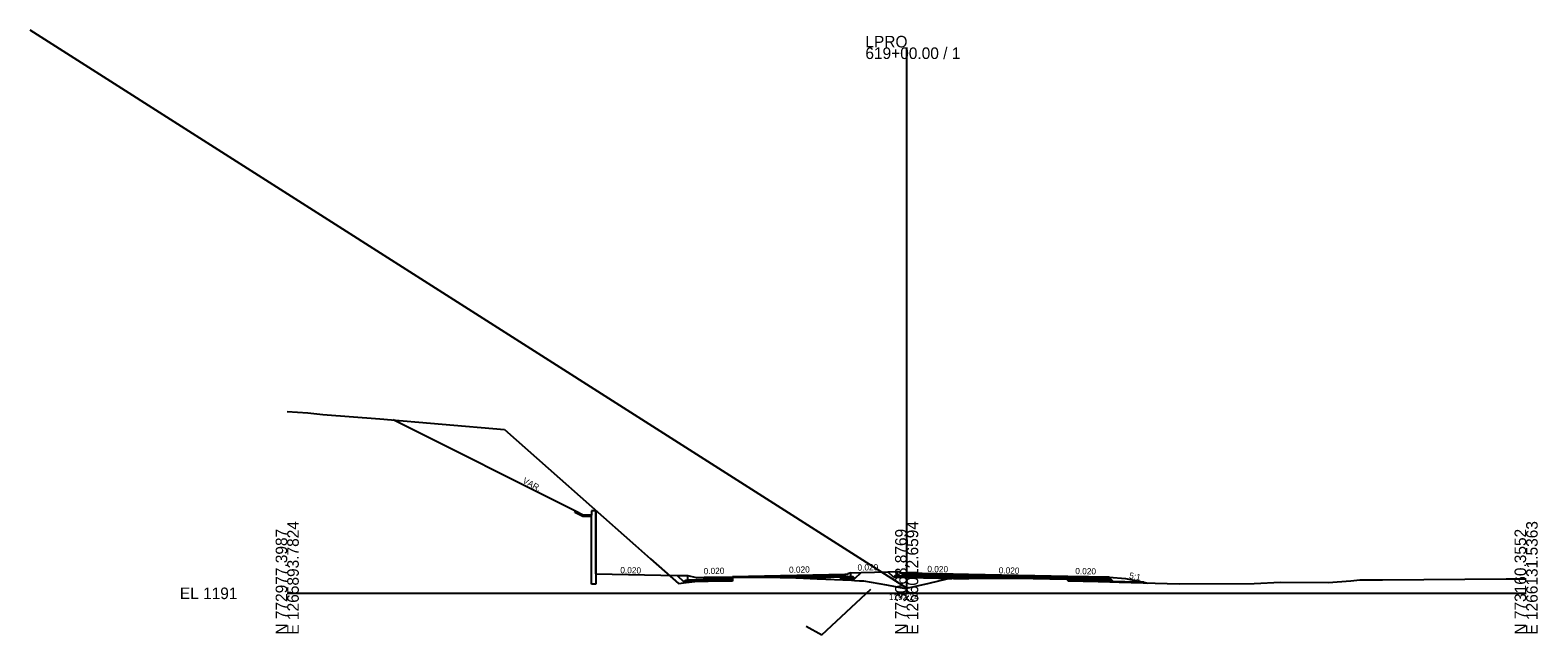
# Model space of a CAD drawing. Extents: x -3833 to 1267678, y -522 to 773248.
# Drawn here: x 2937.8 to 3302.8, y -10 to 136.3 of the extents above; entities that cross this region are included whole.
import ezdxf

# ---------------------------------------------------------------- set-up
doc = ezdxf.new("R2010")
doc.units = 0
for name, color, linetype in [('Exist Cross Section Cell', 7, 'Continuous'), ('Exist XS Center Line Elevation Label', 7, 'Continuous'), ('Exist XS Ground Line', 7, 'Continuous'), ('Prop CMT DNC', 7, 'Continuous'), ('Prop CMT Pvmt Course 1', 7, 'Continuous'), ('Prop CMT Pvmt Course 2', 7, 'Continuous'), ('Prop CMT Pvmt Course 3', 7, 'Continuous'), ('Prop CMT Pvmt Course 4', 7, 'Continuous'), ('Prop CMT Shld Paved Course 1', 7, 'Continuous'), ('Prop CMT Shld Paved Course 2', 7, 'Continuous'), ('Prop CMT Shld Paved Course 4', 7, 'Continuous'), ('Prop CMT Slope Grass', 7, 'Continuous'), ('Prop CMT Subgrade Earthwork', 7, 'Continuous'), ('Prop Conc Curb and Gutter', 7, 'Continuous'), ('Prop Conc Island Cover', 7, 'Continuous'), ('Prop Corridor Mesh Bottom', 7, 'Continuous'), ('Prop XS Ditch Slope Text', 7, 'Continuous'), ('Prop XS Finish Grade', 7, 'Continuous'), ('Prop XS SE Text', 7, 'Continuous'), ('Scratch_Level_1', 7, 'Continuous'), ('Scratch_Level_5', 7, 'Continuous')]:
    doc.layers.add(name, color=color, linetype=linetype)

msp = doc.modelspace()

# ---------------------------------------------------------------- linework, layer by layer
at = {"layer": 'Exist Cross Section Cell'}
for p, q in [((3150, 0), (3150, 132.12)), ((3000, 0), (3150, 0)), ((3150, 0), (3300, 0))]:
    msp.add_line(p, q, dxfattribs=at)
at = {"layer": 'Exist XS Ground Line'}
for p, q in [((3000, 44.04), (3004.97, 43.68)), ((3004.97, 43.68), (3008.66, 43.28)), ((3008.66, 43.28), (3022.44, 42.25)), ((3022.44, 42.25), (3052.63, 39.62)), ((3052.63, 39.62), (3084.3, 11.56)), ((3084.3, 11.56), (3087.95, 8.33)), ((3087.95, 8.33), (3094.75, 2.4)), ((3096.63, 2.63), (3107.07, 3.85)), ((3107.07, 3.85), (3108.26, 3.87)), ((3108.26, 3.87), (3111.3, 3.94)), ((3111.3, 3.94), (3119.34, 3.8)), ((3119.34, 3.8), (3123.3, 3.73)), ((3123.3, 3.73), (3128.3, 3.52)), ((3160.97, 3.61), (3163.36, 3.66)), ((3163.36, 3.66), (3164.79, 3.68)), ((3164.79, 3.68), (3169.2, 3.67)), ((3169.2, 3.67), (3176.55, 3.67)), ((3176.55, 3.67), (3184.64, 3.49)), ((3094.75, 2.4), (3096.63, 2.63)), ((3128.3, 3.52), (3136.63, 3.18)), ((3136.63, 3.18), (3137.39, 3.12)), ((3137.39, 3.12), (3138.58, 3.02)), ((3138.58, 3.02), (3139.51, 3)), ((3139.51, 3), (3145.1, 2.02)), ((3145.1, 2.02), (3149.68, 1.17)), ((3149.68, 1.17), (3150, 1.24)), ((3150, 1.24), (3155.48, 2.44)), ((3155.48, 2.44), (3159.83, 3.5)), ((3159.83, 3.5), (3160.97, 3.61)), ((3184.64, 3.49), (3188.72, 3.39)), ((3188.72, 3.39), (3191.99, 3.14)), ((3191.99, 3.14), (3193.3, 3.04)), ((3193.3, 3.04), (3196.87, 2.88)), ((3196.87, 2.88), (3201.43, 2.68)), ((3201.43, 2.68), (3215.95, 2.27)), ((3215.95, 2.27), (3234.13, 2.4)), ((3234.13, 2.4), (3240.49, 2.66)), ((3240.49, 2.66), (3252.03, 2.59)), ((3252.03, 2.59), (3257.58, 3.02)), ((3257.58, 3.02), (3259.73, 3.25)), ((3259.73, 3.25), (3265.23, 3.29)), ((3265.23, 3.29), (3295.18, 3.53)), ((3295.18, 3.53), (3298.85, 3.53)), ((3298.85, 3.53), (3300, 3.53))]:
    msp.add_line(p, q, dxfattribs=at)
at = {"layer": 'Prop CMT Pvmt Course 1'}
for p, q in [((3135, 4.56), (3107.86, 4.01)), ((3107.86, 3.87), (3135, 4.31)), ((3107.86, 4.01), (3107.86, 4.01)), ((3107.86, 3.76), (3107.86, 3.76)), ((3107.86, 3.76), (3107.86, 3.76)), ((3135, 4.31), (3135, 4.56)), ((3135, 4.31), (3135, 4.31)), ((3189, 4.08), (3165, 4.56)), ((3165, 4.56), (3165, 4.31)), ((3165, 4.31), (3165, 4.31)), ((3165, 4.31), (3189, 3.83)), ((3189, 3.83), (3189, 4.08)), ((3189, 4.08), (3189, 4.08)), ((3189, 3.83), (3189, 3.83)), ((3189, 3.83), (3189, 3.83))]:
    msp.add_line(p, q, dxfattribs=at)
msp.add_lwpolyline([(3107.86, 4.01), (3107.86, 3.86), (3107.86, 3.76)], dxfattribs=at)
at = {"layer": 'Prop CMT Pvmt Course 2'}
for p, q in [((3135, 4.31), (3135, 4.31)), ((3135, 4.31), (3135, 3.98)), ((3135, 3.98), (3135, 3.98)), ((3135, 3.98), (3135, 3.97)), ((3135, 3.97), (3135, 3.97)), ((3150, 4.61), (3149.23, 4.59)), ((3149.23, 4.26), (3150, 4.28)), ((3165, 4.31), (3150, 4.61)), ((3150, 4.28), (3165, 3.97)), ((3165, 3.97), (3165, 4.31)), ((3165, 4.31), (3165, 4.31)), ((3165, 3.97), (3165, 3.97)), ((3165, 3.97), (3165, 3.97)), ((3165, 3.97), (3165, 3.97))]:
    msp.add_line(p, q, dxfattribs=at)
at = {"layer": 'Prop CMT Pvmt Course 3'}
for p, q in [((3137.01, 4.02), (3135, 3.97)), ((3137.46, 3.57), (3137.01, 4.02)), ((3146.94, 4.01), (3147.22, 4.3)), ((3147.22, 4.3), (3149.23, 4.26))]:
    msp.add_line(p, q, dxfattribs=at)
at = {"layer": 'Prop CMT Pvmt Course 4'}
for p, q in [((3134, 4.54), (3134, 3.29)), ((3135, 3.97), (3135, 3.98)), ((3135, 3.97), (3135, 3.97)), ((3147.22, 4.3), (3146.81, 3.88)), ((3146.81, 3.88), (3165, 3.52)), ((3147.72, 4.29), (3147.22, 4.3)), ((3165, 3.97), (3150, 4.28)), ((3165, 3.52), (3165, 3.97)), ((3165, 3.97), (3165, 3.97)), ((3165, 3.97), (3165, 3.97)), ((3134, 3.5), (3137.46, 3.57))]:
    msp.add_line(p, q, dxfattribs=at)
at = {"layer": 'Prop CMT Shld Paved Course 1'}
for p, q in [((3101, 3.88), (3107.86, 4.01)), ((3101, 3.63), (3101, 3.88)), ((3101, 3.88), (3101, 3.88)), ((3107.86, 3.76), (3101, 3.63)), ((3107.86, 3.76), (3107.86, 3.76)), ((3135, 4.56), (3135, 4.56)), ((3135, 4.56), (3135, 4.31)), ((3135, 4.31), (3135, 4.31)), ((3135, 4.31), (3135, 4.31)), ((3150, 4.86), (3149.23, 4.84)), ((3149.23, 4.59), (3150, 4.61)), ((3165, 4.56), (3150, 4.86)), ((3150, 4.61), (3165, 4.31)), ((3165, 4.31), (3165, 4.56)), ((3165, 4.56), (3165, 4.56)), ((3165, 4.31), (3165, 4.31)), ((3165, 4.31), (3165, 4.31)), ((3189, 4.08), (3189, 3.83)), ((3199, 3.88), (3189, 4.08)), ((3189, 3.83), (3199.26, 3.62)), ((3199.26, 3.62), (3199, 3.88)), ((3101, 3.63), (3101, 3.63)), ((3101, 3.63), (3101, 3.63))]:
    msp.add_line(p, q, dxfattribs=at)
msp.add_lwpolyline([(3107.86, 4.01), (3107.86, 3.86), (3107.86, 3.86), (3107.86, 3.86)], dxfattribs=at)
at = {"layer": 'Prop CMT Shld Paved Course 2'}
for p, q in [((3101, 3.63), (3107.86, 3.76)), ((3107.86, 3.86), (3108.3, 3.88)), ((3108.3, 3.88), (3107.86, 3.86)), ((3107.86, 3.76), (3107.86, 3.86)), ((3107.86, 3.86), (3107.86, 3.76)), ((3107.86, 3.76), (3107.86, 3.43)), ((3107.86, 3.76), (3107.86, 3.76)), ((3107.86, 3.76), (3107.86, 3.76)), ((3108.3, 3.88), (3109.24, 3.9)), ((3109.24, 3.9), (3108.3, 3.88)), ((3109.24, 3.9), (3111.18, 3.94)), ((3111.18, 3.94), (3109.24, 3.9)), ((3111.18, 3.94), (3111.3, 3.94)), ((3111.45, 3.94), (3111.18, 3.94)), ((3111.3, 3.94), (3114.14, 3.89)), ((3119.34, 3.99), (3111.45, 3.94)), ((3114.14, 3.89), (3114.14, 3.89)), ((3114.14, 3.89), (3119.34, 3.8)), ((3123.3, 4.07), (3119.34, 3.99)), ((3119.34, 3.99), (3119.34, 3.99)), ((3119.34, 3.8), (3119.34, 3.8)), ((3119.34, 3.8), (3123.15, 3.74)), ((3123.15, 3.74), (3123.15, 3.74)), ((3123.15, 3.74), (3123.3, 3.74)), ((3128.3, 4.17), (3123.3, 4.07)), ((3123.3, 4.07), (3123.3, 4.07)), ((3123.3, 4.07), (3123.3, 4.07)), ((3123.3, 3.74), (3128.3, 3.84)), ((3123.3, 3.74), (3123.3, 3.74)), ((3123.3, 3.74), (3123.3, 3.74)), ((3135, 4.31), (3128.3, 4.17)), ((3128.3, 4.17), (3128.3, 4.17)), ((3128.3, 3.84), (3135, 3.97)), ((3128.3, 3.84), (3128.3, 3.84)), ((3135, 3.97), (3135, 4.31)), ((3135, 3.97), (3135, 3.97)), ((3165, 3.97), (3165, 4.31)), ((3165, 4.31), (3165, 4.31)), ((3165, 4.31), (3169.2, 4.22)), ((3169.2, 3.89), (3165, 3.97)), ((3165, 3.97), (3165, 3.97)), ((3165, 3.97), (3165, 3.97)), ((3169.2, 4.22), (3169.2, 4.22)), ((3169.2, 4.22), (3176.55, 4.08)), ((3176.55, 3.74), (3169.2, 3.89)), ((3169.2, 3.89), (3169.2, 3.89)), ((3176.55, 4.08), (3184.64, 3.91)), ((3184.64, 3.58), (3176.55, 3.74)), ((3184.64, 3.91), (3184.64, 3.91)), ((3184.64, 3.91), (3188.72, 3.83)), ((3188.72, 3.83), (3188.72, 3.83)), ((3188.72, 3.83), (3189, 3.83)), ((3189, 3.83), (3189, 3.83)), ((3189, 3.83), (3189, 3.49)), ((3189, 3.83), (3189, 3.5)), ((3199.26, 3.62), (3189, 3.83)), ((3101, 3.29), (3101, 3.63)), ((3107.86, 3.43), (3101, 3.29)), ((3188.72, 3.5), (3184.64, 3.58)), ((3184.64, 3.58), (3184.64, 3.58)), ((3189, 3.49), (3188.72, 3.5)), ((3188.72, 3.5), (3188.72, 3.5)), ((3189, 3.5), (3199.59, 3.29)), ((3189, 3.49), (3189, 3.49)), ((3189, 3.49), (3189, 3.49)), ((3199.59, 3.29), (3199.26, 3.62))]:
    msp.add_line(p, q, dxfattribs=at)
at = {"layer": 'Prop CMT Shld Paved Course 4'}
for p, q in [((3096.03, 2.74), (3096.5, 3.2)), ((3107.86, 2.97), (3096.03, 2.74)), ((3096.5, 3.2), (3097, 3.21)), ((3097, 3.21), (3107.86, 3.43)), ((3107.86, 3.43), (3107.86, 2.97)), ((3189, 3.5), (3189, 3.04)), ((3199.09, 3.3), (3189, 3.5)), ((3189, 3.04), (3200.06, 2.82)), ((3199.59, 3.29), (3199.09, 3.3)), ((3200.06, 2.82), (3199.59, 3.29))]:
    msp.add_line(p, q, dxfattribs=at)
at = {"layer": 'Prop CMT Slope Grass'}
for p, q in [((3094.42, 4.35), (3097, 4.3)), ((3136.51, 4.99), (3138.95, 5.05)), ((3145.47, 5.22), (3147.56, 5.27)), ((3199, 3.88), (3203, 3.56)), ((3203, 3.56), (3207.45, 2.67))]:
    msp.add_line(p, q, dxfattribs=at)
at = {"layer": 'Prop CMT Subgrade Earthwork'}
for p, q in [((3094.42, 4.35), (3096.03, 2.74)), ((3107.86, 3.86), (3107.86, 2.97)), ((3137.46, 3.57), (3138.95, 5.05)), ((3146.81, 3.88), (3145.47, 5.22)), ((3165, 3.52), (3146.81, 3.88)), ((3165, 3.68), (3165, 3.52)), ((3107.86, 2.97), (3096.03, 2.74)), ((3137.46, 3.57), (3134, 3.5)), ((3134, 3.5), (3134, 3.29)), ((3189, 3.37), (3189, 3.04)), ((3207.45, 2.67), (3189, 3.04))]:
    msp.add_line(p, q, dxfattribs=at)
at = {"layer": 'Prop Conc Curb and Gutter'}
for p, q in [((3069.62, 19.6), (3069.77, 19.9)), ((3071.62, 18.6), (3069.62, 19.6)), ((3071.7, 18.93), (3069.77, 19.9)), ((3073.7, 18.6), (3071.62, 18.6)), ((3073.7, 18.93), (3071.7, 18.93)), ((3073.69, 2.21), (3073.7, 18.93)), ((3074.7, 19.93), (3073.7, 19.93)), ((3073.7, 19.93), (3073.7, 18.93)), ((3074.7, 19.93), (3074.7, 19.94)), ((3074.7, 19.94), (3074.7, 19.93)), ((3074.7, 19.93), (3074.7, 19.93)), ((3074.7, 19.93), (3074.7, 19.93)), ((3074.7, 19.93), (3074.7, 3.35)), ((3097, 3.21), (3097, 4.3)), ((3097, 4.3), (3099, 3.8)), ((3099, 3.8), (3101, 3.88)), ((3099, 3.8), (3099, 3.8)), ((3099, 3.8), (3099, 3.8)), ((3101, 3.88), (3101, 3.29)), ((3135.75, 4.57), (3135, 4.56)), ((3135, 4.56), (3135, 4.56)), ((3135, 4.56), (3135, 3.97)), ((3135, 3.97), (3136.51, 4.01)), ((3135, 3.97), (3135, 3.97)), ((3135, 3.97), (3135, 3.97)), ((3136.51, 4.99), (3135.75, 4.74)), ((3135.75, 4.74), (3135.75, 4.74)), ((3135.75, 4.74), (3135.75, 4.57)), ((3135.75, 4.57), (3135.75, 4.57)), ((3136.51, 4.01), (3136.51, 4.99)), ((3136.51, 4.01), (3136.51, 4.01)), ((3148.48, 5.03), (3147.72, 5.27)), ((3147.72, 5.27), (3147.72, 4.29)), ((3147.72, 4.29), (3147.72, 4.29)), ((3147.72, 4.29), (3149.23, 4.26)), ((3148.48, 5.02), (3148.48, 5.03)), ((3148.48, 4.86), (3148.48, 5.02)), ((3149.23, 4.84), (3148.48, 4.86)), ((3148.48, 4.86), (3148.48, 4.86)), ((3149.23, 4.26), (3149.23, 4.84)), ((3149.23, 4.84), (3149.23, 4.84)), ((3149.23, 4.26), (3149.23, 4.26)), ((3149.23, 4.26), (3149.23, 4.26)), ((3074.7, 2.21), (3073.69, 2.21)), ((3073.69, 2.21), (3073.69, 2.21)), ((3074.7, 3.35), (3074.7, 2.22)), ((3074.7, 2.22), (3074.7, 2.21)), ((3099, 3.25), (3097, 3.21)), ((3097, 3.21), (3097, 3.21)), ((3097, 3.21), (3097, 3.21)), ((3101, 3.29), (3099, 3.25)), ((3099, 3.25), (3099, 3.25)), ((3101, 3.29), (3101, 3.29))]:
    msp.add_line(p, q, dxfattribs=at)
at = {"layer": 'Prop Conc Island Cover'}
for p, q in [((3136.51, 4.74), (3136.51, 4.99)), ((3147.72, 5.27), (3147.72, 5.02))]:
    msp.add_line(p, q, dxfattribs=at)
at = {"layer": 'Prop Corridor Mesh Bottom'}
for p, q in [((3135, 4.56), (3135, 4.31)), ((3165, 4.56), (3165, 4.31)), ((3189, 4.08), (3189, 3.83))]:
    msp.add_line(p, q, dxfattribs=at)
msp.add_lwpolyline([(3107.86, 4.01), (3107.86, 3.86), (3107.86, 3.76)], dxfattribs=at)
at = {"layer": 'Prop XS Finish Grade'}
for p, q in [((3069.77, 19.9), (3025.63, 41.97)), ((3071.7, 18.93), (3069.77, 19.9)), ((3073.7, 18.93), (3071.7, 18.93)), ((3074.7, 19.93), (3073.7, 19.93)), ((3073.7, 19.93), (3073.7, 18.93)), ((3074.7, 4.74), (3074.7, 19.93)), ((3074.7, 4.74), (3094.42, 4.35)), ((3138.95, 5.05), (3145.47, 5.22)), ((3147.56, 5.27), (3147.72, 5.27)), ((3207.45, 2.67), (3208.37, 2.48))]:
    msp.add_line(p, q, dxfattribs=at)
at = {"layer": 'Scratch_Level_1'}
msp.add_line((3150, 1.24), (2937.75, 136.3), dxfattribs=at)
at = {"layer": 'Scratch_Level_5'}
for p, q in [((3129.47, -10.05), (3141.33, 0.98)), ((3125.69, -7.94), (3129.47, -10.05))]:
    msp.add_line(p, q, dxfattribs=at)

# ---------------------------------------------------------------- texts
at = {"layer": 'Exist Cross Section Cell'}
for s, p in [('619+00.00 / 1', (3140, 129.32)), ('LPRO', (3140, 132.12)), ('EL 1191', (2974, -1.4))]:
    msp.add_text(s, height=2.8, dxfattribs=at).set_placement(p)
for s, p in [('N 772977.3987', (3000, -10)), ('E 1265893.7824', (3002.8, -10)), ('N 773068.8769', (3150, -10)), ('E 1266012.6594', (3152.8, -10)), ('N 773160.3552', (3300, -10)), ('E 1266131.5363', (3302.8, -10))]:
    msp.add_text(s, height=2.8, rotation=90, dxfattribs=at).set_placement(p)
at = {"layer": 'Exist XS Center Line Elevation Label'}
msp.add_text('1192.24', height=1.5, dxfattribs=at).set_placement((3145.69, -1.63))
at = {"layer": 'Prop CMT DNC'}
for p in [(3090.8, 5.85), (3099, 3.8), (3101, 3.88), (3101, 3.88), (3107.86, 4.01), (3107.86, 4.01), (3135, 4.56), (3135, 4.56), (3135.75, 4.57), (3148.48, 4.86), (3150, 4.86), (3165, 4.56), (3165, 4.56), (3189, 4.08), (3189, 4.08), (3199, 3.88)]:
    msp.add_text('X', height=0.00025, dxfattribs=at).set_placement(p)
at = {"layer": 'Prop XS Ditch Slope Text'}
for s, rotation, p in [('VAR.', 331.3485, (3056.86, 26.82)), ('5:1', 348.3072, (3203.78, 3.64))]:
    msp.add_text(s, height=1.5, rotation=rotation, dxfattribs=at).set_placement(p)
at = {"layer": 'Prop XS SE Text'}
for rotation, p in [(358.8542, (3080.65, 4.88)), (1.397, (3100.86, 4.61)), (1.397, (3121.53, 4.93)), (1.299, (3138.11, 5.48)), (358.8542, (3155, 5.16)), (358.8542, (3172.28, 4.83)), (358.8542, (3190.82, 4.66))]:
    msp.add_text('0.020', height=1.5, rotation=rotation, dxfattribs=at).set_placement(p)

doc.saveas('drawing.dxf')
